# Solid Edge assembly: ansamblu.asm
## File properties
Author: Ionut
Template: Normal.asm
Last saved by: Ionut Lambrescu
Revision: 23
Application: Solid Edge
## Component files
baza.par
culisa2.par
culisa1.par
culisa3.par
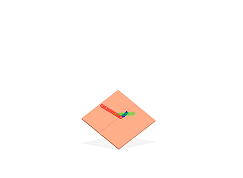
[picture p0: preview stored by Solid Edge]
